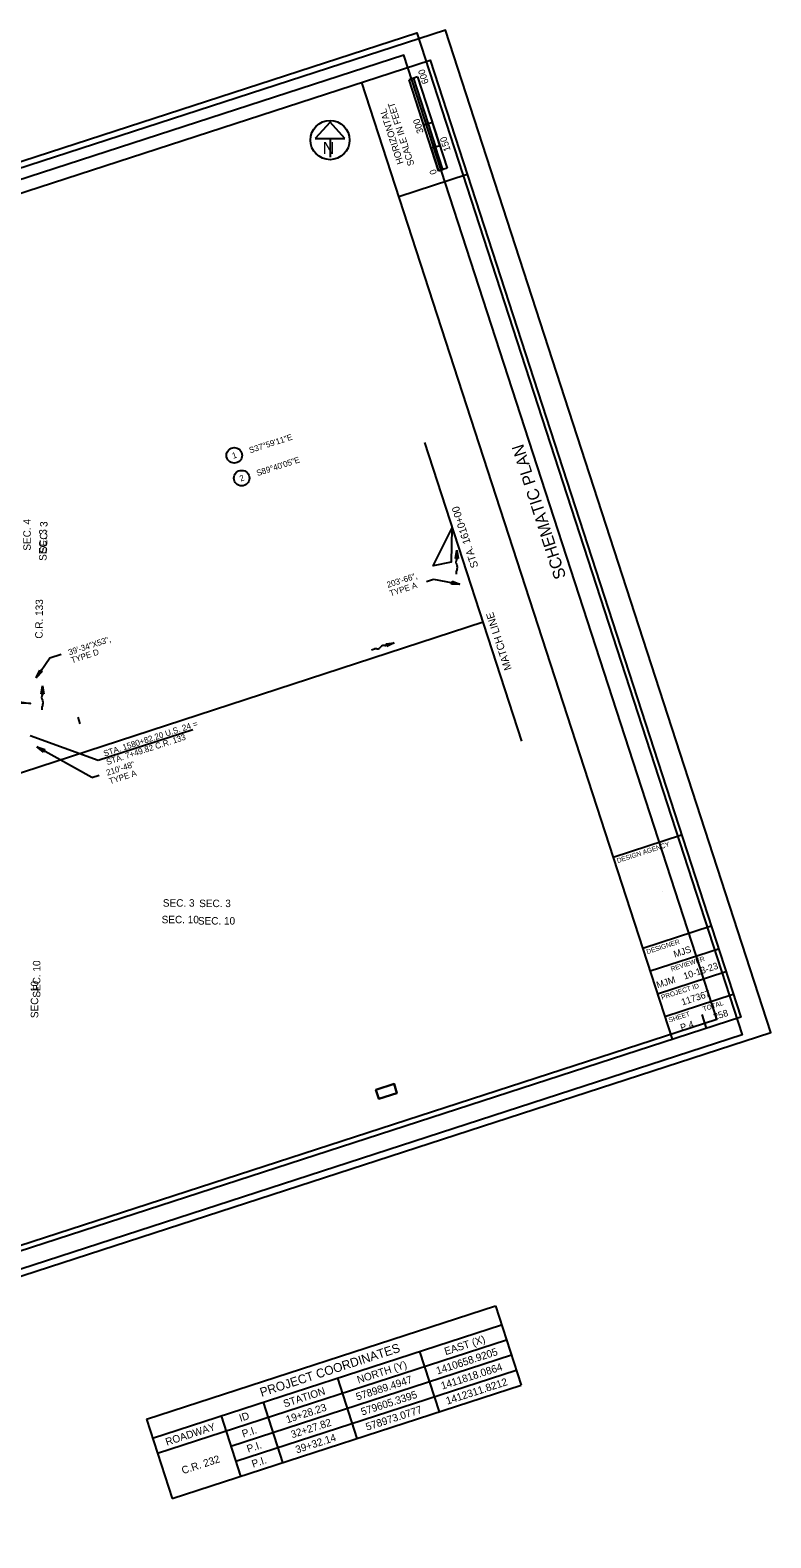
# Model space of a CAD drawing. Extents: x -347538417 to 1419006, y -281760895 to 585039.
# Drawn here: x 1414367 to 1419006, y 575029 to 584472 of the extents above; entities that cross this region are included whole.
import ezdxf

# ---------------------------------------------------------------- set-up
doc = ezdxf.new("R2010")
doc.units = 0
for name, color, linetype in [('HY_X_Wetland_Area', 7, 'Continuous'), ('Level 31', 7, 'Continuous'), ('Level 63', 7, 'Continuous'), ('RD_X_RR_1', 7, 'Continuous'), ('SH_Border', 7, 'Continuous'), ('SH_Cut_Line', 7, 'Continuous'), ('SH_Data', 7, 'Continuous'), ('SH_Masking', 7, 'Continuous'), ('SH_Text', 7, 'Continuous'), ('TX_P_Misc', 7, 'Continuous')]:
    doc.layers.add(name, color=color, linetype=linetype)

msp = doc.modelspace()

# ---------------------------------------------------------------- linework, layer by layer
at = {"layer": 'HY_X_Wetland_Area'}
for points in [[(1417011.5, 581359.7), (1417008.1, 581352.7), (1417008.1, 581352.7), (1417008.1, 581352.7), (1417008.1, 581352.7), (1417008.1, 581352.7), (1417004.8, 581140.1), (1417004.8, 581140.1), (1417004.8, 581140.1), (1417004.8, 581140.1), (1416891.9, 581116.2), (1416891.9, 581116.2), (1416891.9, 581116.2), (1416891.9, 581116.2), (1416891.9, 581116.2), (1416891.9, 581116.2), (1417011.5, 581359.7), (1417011.5, 581359.7)], [(1416531.9, 577835.2), (1416550.5, 577778.2), (1416664.6, 577815.2), (1416646.1, 577872.3)], [(1416531.9, 577835.2), (1416646.1, 577872.3), (1416646.1, 577872.3), (1416646.1, 577872.3), (1416646.1, 577872.3), (1416646.1, 577872.3), (1416664.6, 577815.2), (1416664.6, 577815.2), (1416664.6, 577815.2), (1416664.6, 577815.2), (1416550.5, 577778.2), (1416550.5, 577778.2), (1416550.5, 577778.2), (1416550.5, 577778.2), (1416550.5, 577778.2), (1416550.5, 577778.2), (1416531.9, 577835.2), (1416531.9, 577835.2)]]:
    msp.add_lwpolyline(points, close=True, dxfattribs=at)
at = {"layer": 'Level 31'}
for p, q in [((1417030.6, 581163.2), (1417039.5, 581214.8)), ((1417039.2, 581161.8), (1417039.5, 581214.8)), ((1417039.5, 581214.8), (1417047.8, 581163.2)), ((1417047.8, 581163.2), (1417030.6, 581163.2)), ((1417037.5, 581153.3), (1417035.7, 581149.2)), ((1417035.7, 581132.1), (1417039.2, 581123.5)), ((1417039.2, 581123.5), (1417042.3, 581115.8)), ((1417038.1, 581064.8), (1417038.2, 581085.7)), ((1417041.9, 581097.9), (1417040, 581093.6)), ((1416504.7, 580590), (1416524.7, 580596.4)), ((1416537.4, 580596.7), (1416532.8, 580597.2)), ((1416560.8, 580607.3), (1416554.5, 580601.9)), ((1416567.9, 580613.3), (1416560.8, 580607.3)), ((1416588.6, 580618.2), (1416584.2, 580618.6)), ((1416595.9, 580627.9), (1416647.7, 580635.5)), ((1416601.2, 580611.5), (1416595.9, 580627.9)), ((1416597.3, 580619.2), (1416647.7, 580635.5)), ((1416647.7, 580635.5), (1416601.2, 580611.5)), ((1414435.2, 580314.5), (1414444.1, 580366)), ((1414443.8, 580313.1), (1414444.1, 580366)), ((1414444.1, 580366), (1414452.4, 580314.4)), ((1414452.4, 580314.4), (1414435.2, 580314.5)), ((1414440.2, 580283.3), (1414443.7, 580274.7)), ((1414442, 580304.5), (1414440.3, 580300.4)), ((1414443.7, 580274.7), (1414446.9, 580267)), ((1414442.7, 580216), (1414442.8, 580237)), ((1414446.5, 580249.1), (1414444.5, 580244.9))]:
    msp.add_line(p, q, dxfattribs=at)
for centre, radius, start, end in [((1417056.4, 581140.5), 22.4, 157.28387, 202.12773), ((1417016.8, 581161.9), 22.4, 337.3227, 359.68272), ((1417021.6, 581107.3), 22.4, 335.15003, 22.25849), ((1417057.4, 581085.6), 19.2, 155.19991, 179.68272), ((1416530.6, 580578.1), 19.2, 83.42478, 107.90759), ((1416540, 580618.9), 22.4, 263.3749, 310.48336), ((1416582.4, 580596.2), 22.4, 85.50874, 130.35259), ((1416590.4, 580640.5), 22.4, 265.54757, 287.90759), ((1414461, 580291.8), 22.4, 157.28387, 202.12773), ((1414421.4, 580313.2), 22.4, 337.3227, 359.68272), ((1414426.2, 580258.5), 22.4, 335.15003, 22.25849), ((1414462, 580236.9), 19.2, 155.19991, 179.68272)]:
    msp.add_arc(centre, radius, start, end, dxfattribs=at)
at = {"layer": 'Level 63'}
for points in [[(1407088.6, 581305.9), (1416789.4, 584455.4), (1418827.2, 578178.6), (1409126.4, 575029.2)], [(1409195.4, 575203), (1418668.6, 578278.5), (1416708.4, 584316.3), (1407235.1, 581240.7)]]:
    msp.add_lwpolyline(points, close=True, dxfattribs=at)
at = {"layer": 'RD_X_RR_1'}
msp.add_lwpolyline([(1417204.9, 580764), (1411942.1, 579047.2)], dxfattribs=at)
at = {"layer": 'SH_Border'}
for p, q in [((1418389.4, 578152), (1416444, 584144.1)), ((1416675.6, 583430.7), (1417103.6, 583569.7)), ((1418018.8, 579293.3), (1418446.8, 579432.3)), ((1418204.1, 578722.6), (1418632.1, 578861.6)), ((1418250.4, 578580), (1418678.4, 578718.9)), ((1418296.7, 578437.3), (1418724.7, 578576.2)), ((1418343, 578294.6), (1418771.1, 578433.6))]:
    msp.add_line(p, q, dxfattribs=at)
msp.add_lwpolyline([(1407741.1, 581318.6), (1416872, 584283), (1418817.4, 578290.9), (1409686.5, 575326.5)], close=True, dxfattribs=at)
at = {"layer": 'SH_Cut_Line'}
msp.add_lwpolyline([(1409304.8, 575044.9), (1419006.4, 578194.6), (1416968.3, 584472), (1407266.8, 581322.3)], close=True, dxfattribs=at)
at = {"layer": 'SH_Data'}
for p, q in [((1416793.6, 584178.7), (1416740.1, 584161.4)), ((1416740.1, 584161.4), (1416766.7, 584170)), ((1416925.4, 583590.7), (1416740.1, 584161.4)), ((1416832.7, 583876), (1416740.1, 584161.4)), ((1416766.7, 584170), (1416767, 584170.1)), ((1416767, 584170.1), (1416859.6, 583884.7)), ((1416793.6, 584178.7), (1416978.9, 583608)), ((1416859.6, 583884.7), (1416832.7, 583876)), ((1416886, 583893.3), (1416859.4, 583884.7)), ((1416859.4, 583884.7), (1416905.7, 583742)), ((1416932.3, 583750.6), (1416886, 583893.3)), ((1416905.7, 583742), (1416879.1, 583733.3)), ((1416879.1, 583733.3), (1416925.4, 583590.7)), ((1416905.7, 583742), (1416932.3, 583750.6)), ((1416952, 583599.3), (1416905.7, 583742)), ((1416978.9, 583608), (1416925.4, 583590.7)), ((1416925.4, 583590.7), (1416952, 583599.3)), ((1418325.5, 579077.4), (1418325.5, 579077.4)), ((1418603.4, 578221.4), (1418575.6, 578307)), ((1418480.2, 578236.6), (1418480.2, 578236.6))]:
    msp.add_line(p, q, dxfattribs=at)
at = {"layer": 'SH_Masking'}
msp.add_circle((1416245, 583783.8), 123, dxfattribs=at)
at = {"layer": 'SH_Text'}
for p, q in [((1416245, 583895.9), (1416152.7, 583793.5)), ((1416337.3, 583793.5), (1416245, 583895.9)), ((1416152.7, 583793.5), (1416337.3, 583793.5)), ((1416245, 583793.5), (1416245, 583677.5)), ((1417446.9, 580018.9), (1416839.3, 581890.3)), ((1416848.8, 581018.7), (1416894.2, 581033.4)), ((1416894.2, 581033.4), (1417058.6, 581001.8)), ((1417006.3, 581003.1), (1417009.6, 581020)), ((1417009.6, 581020), (1417058.6, 581001.8)), ((1417058.6, 581001.8), (1417006.3, 581003.1)), ((1414405, 580416.5), (1414427.2, 580463.9)), ((1414441.3, 580454.2), (1414405, 580416.5)), ((1414427.2, 580463.9), (1414441.3, 580454.2)), ((1414664.8, 580169), (1414678.6, 580126.6)), ((1414793.6, 579899), (1415386.4, 580091.5)), ((1414367.9, 580053.6), (1414793.6, 579899)), ((1414753.7, 579790.8), (1414409.1, 579983.7)), ((1414449.9, 579951), (1414409.1, 579983.7)), ((1414409.1, 579983.7), (1414458.3, 579966)), ((1414458.3, 579966), (1414449.9, 579951)), ((1414753.7, 579790.8), (1414799.1, 579805.5)), ((1415094.6, 575773.5), (1417280.9, 576483.3)), ((1417280.9, 576483.3), (1417442.4, 575986)), ((1415133.6, 575653.5), (1417319.9, 576363.3)), ((1415164.2, 575559.1), (1417350.5, 576269)), ((1415623.5, 575604), (1417381.2, 576174.6)), ((1416805.5, 576196.3), (1416928, 575819)), ((1415654.1, 575509.7), (1417411.8, 576080.3)), ((1416291.1, 576029.2), (1416413.5, 575652)), ((1415256.1, 575276.2), (1417442.4, 575986)), ((1415825.5, 575878.1), (1415948, 575500.8)), ((1415094.6, 575773.5), (1415256.1, 575276.2)), ((1415562.3, 575792.6), (1415684.7, 575415.4))]:
    msp.add_line(p, q, dxfattribs=at)
msp.add_lwpolyline([(1414405, 580416.5), (1414490.4, 580540.7), (1414561.7, 580563.9)], dxfattribs=at)
msp.add_lwpolyline([(1413883.8, 580329.8), (1414370, 580255.8), (1413902.9, 580270.9)], close=True, dxfattribs=at)
for centre, radius in [((1416245, 583783.8), 123), ((1415645.5, 581808.9), 48.8), ((1415691.8, 581666.2), 48.8)]:
    msp.add_circle(centre, radius, dxfattribs=at)

# ---------------------------------------------------------------- texts
at = {"layer": 'SH_Data'}
for s, height, rotation, p in [('600', 42, 107.9864, (1416864.2, 584142.3)), ('HORIZONTAL', 42, 107.9864, (1416707.1, 583639.8)), ('SCALE IN FEET', 42, 107.9864, (1416774.2, 583629.6)), ('300', 42, 107.9864, (1416832.4, 583832.4)), ('150', 42, 107.9864, (1417001.2, 583720.1)), ('0', 42, 107.9864, (1416915.8, 583575.3)), ('SCHEMATIC PLAN', 75, 107.9864, (1417725.2, 581047.7)), ('DESIGN AGENCY', 30, 17.9864, (1418047, 579255.1)), ('DESIGNER', 30, 17.9864, (1418232.3, 578684.5)), ('REVIEWER', 30, 17.9864, (1418384.7, 578576.2)), ('MJS', 42, 17.9864, (1418404.4, 578663.1)), ('10-13-23', 42, 17.9864, (1418466.5, 578525.5)), ('MJM', 42, 17.9864, (1418297.1, 578470.5)), ('PROJECT ID', 30, 17.9864, (1418324.9, 578399.1)), ('117367', 42, 17.9864, (1418453.1, 578363.5)), ('TOTAL', 30, 17.9864, (1418585.2, 578325.9)), ('SHEET', 30, 17.9864, (1418371.2, 578256.5)), ('258', 42, 17.9864, (1418654.1, 578271)), ('P.4', 42, 17.9864, (1418447.4, 578203.9))]:
    msp.add_text(s, height=height, rotation=rotation, dxfattribs=at).set_placement(p)
at = {"layer": 'SH_Text'}
for s, height, rotation, p in [('N', 75, 0.00095, (1416199.6, 583696.4)), ('S37°59\'11"E', 37.5, 17.9864, (1415745.2, 581821.5)), ('1', 37.5, 17.9864, (1415638.7, 581787)), ('S89°40\'05"E', 37.5, 17.9864, (1415791.5, 581678.9)), ('2', 37.5, 17.9864, (1415685.2, 581644.3)), ('MATCH LINE                 STA. 1610+00', 46.8, 107.98637, (1417382.9, 580470.9)), ('SEC. 3', 46.8, 90, (1414469.6, 581148.4)), ('203\'-66",', 37.5, 17.9864, (1416607.4, 580978.6)), ('TYPE A', 37.5, 17.9864, (1416624.7, 580925.1)), ('C.R. 133', 46.8, 89.28304, (1414444.8, 580660.5)), ('39\'-34"X53",', 37.5, 17.9864, (1414612.9, 580556.3)), ('TYPE D', 37.5, 17.9864, (1414629.1, 580506.4)), ('STA. 1580+82.20 U.S. 24 =', 37.5, 17.9864, (1414833.2, 579922.2)), ('STA. 7+49.82 C.R. 133', 37.5, 17.9864, (1414850.5, 579868.7)), ('210\'-48"', 37.5, 17.9864, (1414850.3, 579802.1)), ('TYPE A', 37.5, 17.9864, (1414867.6, 579748.6)), ('SEC. 10', 46.8, 90, (1414430.6, 578412.4)), ('EAST (X)', 46.87, 17.9864, (1416970, 576172.9)), ('PROJECT COORDINATES', 55.889, 17.9864, (1415816.4, 575912.1)), ('1410658.9205', 46.875, 17.9864, (1416918.5, 576051.9)), ('NORTH (Y)', 46.87, 17.9864, (1416423.1, 575995.3)), ('1411818.0864', 46.875, 17.9864, (1416948.1, 575957.3)), ('578989.4947', 46.875, 17.9864, (1416416.3, 575888.9)), ('1412311.8212', 46.875, 17.9864, (1416979.7, 575863.3)), ('STATION', 46.87, 17.9864, (1415961, 575845.3)), ('579605.3395', 46.875, 17.9864, (1416447.3, 575794.7)), ('19+28.23', 46.87, 17.9864, (1415977.4, 575746.4)), ('578973.0777', 46.875, 17.9864, (1416477.5, 575700.2)), ('ROADWAY', 46.87, 17.9864, (1415223.2, 575605.8)), ('ID', 46.87, 17.9864, (1415684.6, 575755.6)), ('32+27.82', 46.87, 17.9864, (1416007.9, 575652)), ('P.I.', 46.87, 17.9864, (1415701.9, 575656.9)), (' 39+32.14 ', 46.87, 17.9864, (1416020.7, 575551.9)), ('C.R. 232', 46.87, 17.9864, (1415324.4, 575427.5)), ('P.I.', 46.87, 17.9864, (1415732.5, 575562.6)), ('P.I.', 46.87, 17.9864, (1415763.1, 575468.3))]:
    msp.add_text(s, height=height, rotation=rotation, dxfattribs=at).set_placement(p)
for s, p in [('SEC. 3', (1415425.6, 578979.5)), ('SEC. 10', (1415417.5, 578870.2))]:
    msp.add_text(s, height=46.8, dxfattribs=at).set_placement(p)
at = {"layer": 'TX_P_Misc'}
for s, rotation, p in [('SEC. 4', 90, (1414370.6, 581212)), ('SEC. 3', 89.08584, (1414472.5, 581196.7)), ('SEC. 10', 90, (1414417.5, 578284.3))]:
    msp.add_text(s, height=46.8, rotation=rotation, dxfattribs=at).set_placement(p)
for s, p in [('SEC. 3', (1415198.2, 578982.3)), ('SEC. 10', (1415190.5, 578878.3))]:
    msp.add_text(s, height=46.8, dxfattribs=at).set_placement(p)

doc.saveas('drawing.dxf')
